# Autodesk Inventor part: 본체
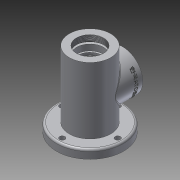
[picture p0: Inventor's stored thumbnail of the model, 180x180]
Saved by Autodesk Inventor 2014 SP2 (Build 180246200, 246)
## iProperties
Created: 2016-08
Part Number: 본체
Material: 알루미늄 6061
Document SubType Name: Modeling
Designer: 이도윤
Density: 2.71 g/cm^3
Appearance: 알루미늄 - 평지
Author: 이도윤
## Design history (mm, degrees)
sketch "스케치1"
  geometry: C1 r 31 at (0, 0); 1 further point
  constraints: 1 centre point, 1 coincident
  dimensions: "d0" = 62 diameter of C1
extrude "돌출1" new body sketch "스케치1" stored distance "d1" = 115; taper "d2" = 0 deg
sketch "스케치2"
  geometry: C1 r 31 at (0, 0) reference; 1 further point
  constraints: 1 coincident
hole "구멍1" sketch "스케치2" at (0, 0) diameter "d3" = 40.376; stored, may be unused: countersink angle "d7" = 90 deg, drill point angle "d9" = 0 deg; dims "d4" = 9, "d5" = 4, "d6" = 2, "d8" = 9
sketch "스케치3"
  geometry: C1 r 20.188 at (0, 0) reference; C2 r 24 at (0, 0)
  constraints: 1 centre point, 1 coincident
  dimensions: "d10" = 48 diameter of C2
extrude "돌출2" cut sketch "스케치3" distance "d11" = 3; taper "d12" = 0 deg
sketch "스케치4"
  geometry: C1 r 24 at (0, 0) reference; C2 r 20 at (0, 0)
  constraints: 1 centre point, 1 coincident
  dimensions: "d13" = 40 diameter of C2
extrude "돌출3" cut sketch "스케치4" distance "d14" = 9; taper "d15" = 0 deg
sketch "스케치5"
  geometry: C1 r 20 at (0, 0) reference; C2 r 17.5 at (0, 0)
  constraints: 1 centre point, 1 coincident
  dimensions: "d16" = 35 diameter of C2
extrude "돌출4" cut sketch "스케치5" distance "d17" = 3.25; taper "d18" = 0 deg
sketch "스케치6"
  geometry: C1 r 17.5 at (0, 0) reference; C2 r 18.5 at (0, 0)
  constraints: 1 centre point, 1 coincident
  dimensions: "d19" = 37 diameter of C2
extrude "돌출5" cut sketch "스케치6" distance "d20" = 1.75; taper "d21" = 0 deg
sketch "스케치8"
  geometry: C1 r 18.5 at (0, 0) reference; C2 r 17.5 at (0, 0)
  constraints: 1 centre point, 1 coincident
  dimensions: "d25" = 35 diameter of C2
extrude "돌출7" cut sketch "스케치8" distance "d26" = 20; taper "d27" = 0 deg
node "작업 평면1"
sketch "스케치9"
  geometry: L1 (31, 57.5)-(-31, 57.5) reference; C1 r 30 at (0, 1.5); 2 further points
  constraints: 1 centre point, 1 midpoint, 1 vertical alignment
  dimensions: "d30" = 60 diameter of C1; "d31" = 56 distance from line of C1.centre L1
extrude "돌출8" join sketch "스케치9" stored distance "d32" = 20; taper "d33" = 0 deg
node "작업 평면2"
sketch "스케치10"
  geometry: C1 r 26 at (0, 0); 1 further point
  constraints: 1 centre point, 1 coincident
  dimensions: "d35" = 52 diameter of C1
extrude "돌출9" cut sketch "스케치10" stored distance "d36" = 38; taper "d37" = 0 deg
sketch "스케치11"
  geometry: C1 r 26 at (0, 0) reference; C2 r 17.5 at (0, 0)
  constraints: 1 centre point, 1 coincident
  dimensions: "d38" = 35 diameter of C2
extrude "돌출10" cut sketch "스케치11" distance "d39" = 11; taper "d40" = 0 deg
sketch "스케치12"
  geometry: C1 r 30 at (0, 0) reference; C2 r 19 at (0, 0); 1 further point
  constraints: 1 centre point, 1 coincident
  dimensions: "d41" = 38 diameter of C2
extrude "돌출11" cut sketch "스케치12" distance "d42" = 45; taper "d43" = 0 deg
sketch "스케치13"
  geometry: C1 r 31 at (0, 0) reference; C2 r 21 at (0, 0)
  constraints: 1 centre point, 1 coincident
  dimensions: "d44" = 42 diameter of C2
node "작업 평면3"
sketch "스케치14"
  geometry: C1 r 16 at (0, 0); 1 further point
  constraints: 1 centre point, 1 coincident
  dimensions: "d46" = 32 diameter of C1
node "작업 평면4"
sketch "스케치15"
  geometry: C1 r 50 at (0, 0); C2 r 4 at (41.5, 0); C3 r 4 at (0, 41.5); C4 r 4 at (-41.5, 0); C5 r 4 at (0, -41.5); 1 further point
  constraints: 5 centre point, 1 coincident, 1 horizontal alignment, 9 other
  dimensions: "d48" = 100 diameter of C1; "d49" = 8 diameter of C2; "d50" = 41.5 distance of C2.centre point (0, 0); "d53" = 360 deg dimension on point (0, 0) C2.centre (derived)
extrude "돌출12" join sketch "스케치15" distance "d55" = 13; taper "d56" = 0 deg
feature "로프트1" dims "d57" = 0, "d58" = 90 deg, "d59" = 0, "d60" = 90 deg
sketch "스케치16"
  geometry: C1 r 17.5 at (0, 0) reference; C2 r 16.5 at (0, 0)
  constraints: 1 centre point, 1 coincident
  dimensions: "d61" = 33 diameter of C2
extrude "돌출13" cut sketch "스케치16" distance "d62" = 5; taper "d63" = 0 deg
sketch "스케치17"
  geometry: C1 r 16.5 at (0, 0) reference; C2 r 10 at (0, 0)
  constraints: 1 centre point, 1 coincident
  dimensions: "d64" = 20 diameter of C2
extrude "돌출14" cut sketch "스케치17" distance "d65" = 2.7; taper "d66" = 0 deg
sketch "스케치18"
  geometry: C1 r 10 at (0, 0) reference; C2 r 12.5 at (0, 0)
  constraints: 1 centre point, 1 coincident
  dimensions: "d67" = 25 diameter of C2
extrude "돌출15" cut sketch "스케치18" distance "d68" = 7.3; taper "d69" = 0 deg
sketch "스케치19"
  geometry: C1 r 19 at (0, 0) reference; 5 further points
  constraints: 1 vertical alignment, 5 other
  dimensions: "d70" = 24 distance of point (0, 24) C1.centre; "d73" = 360 deg dimension on C1.centre point (0, 24) (derived)
hole "구멍2" sketch "스케치19" at (0, 24), (-24, 0), (0, -24), (24, 0) diameter "d75" = 3.242; stored, may be unused: countersink angle "d79" = 90 deg, drill point angle "d81" = 118 deg; dims "d76" = 8, "d77" = 4, "d78" = 2, "d80" = 10
fillet "모깎기1" dims "d82" = 3
fillet "모깎기2" dims "d83" = 3
fillet "모깎기3" dims "d84" = 0.3
chamfer "모따기1" distance "d85" = 0.7; stored, may be unused: second distance "d86" = 2, angle "d87" = 60 deg
chamfer "모따기2" distance "d88" = 1; stored, may be unused: second distance "d89" = 2, angle "d90" = 30 deg
node "작업 평면5"
sketch "스케치20"
  geometry: L1 (49, 31.5)-(49, -28.5) reference; L2 (31, 57.5)-(-31, 57.5) reference; 2 further points
  constraints: 1 other
  dimensions: "d92" = 10 distance from line of L1 point (39, 1.5); "d93" = 56 distance from line of point (39, 1.5) L2
feature "엠보싱1" sketch "스케치20" dims "d0" = 62, "d94" = 0.5, "d95" = 0
chamfer "모따기3" distance "d96" = 1; stored, may be unused: second distance "d97" = 2, angle "d98" = 45 deg
node "솔리드1"
other parameters: "d28" = 49, "d34" = -56, "d45" = -14, "d47" = -3
